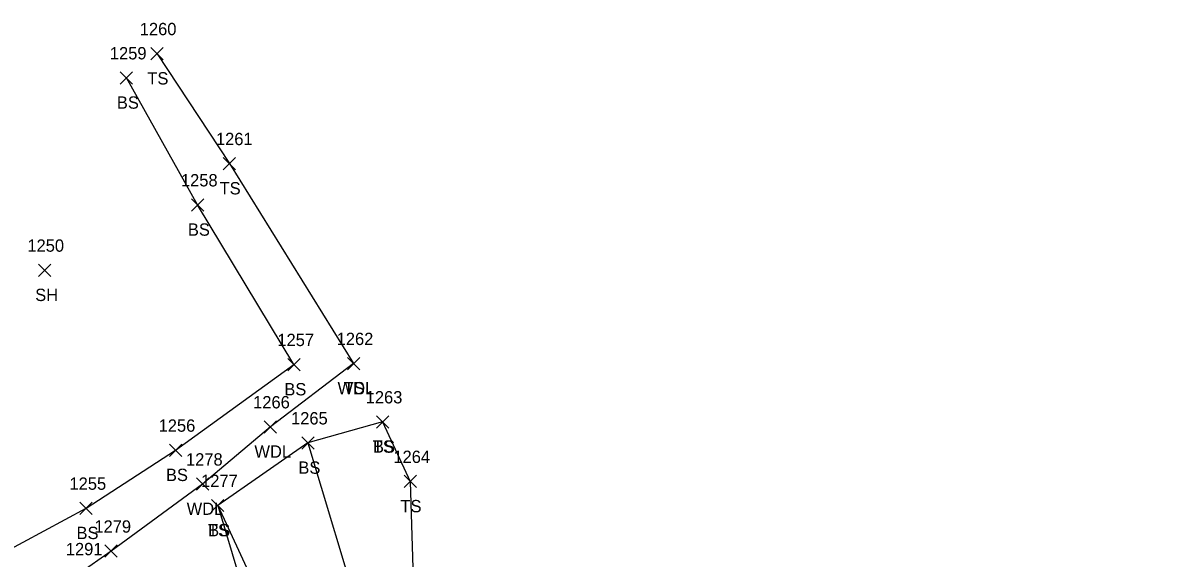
# Model space of a CAD drawing. Extents: x 1505656 to 1508446, y 700805 to 703031.
# Drawn here: x 1506221.6 to 1506405.5, y 702417.6 to 702504.5 of the extents above; entities that cross this region are included whole.
import ezdxf

# ---------------------------------------------------------------- set-up
doc = ezdxf.new("R2010")
doc.units = 0
for name, color, linetype in [('L_A', 7, 'Continuous'), ('L_I', 7, 'Continuous'), ('L_TIC', 7, 'Continuous'), ('LAWA', 7, 'Continuous'), ('LELB', 7, 'Continuous')]:
    doc.layers.add(name, color=color, linetype=linetype)

msp = doc.modelspace()

# ---------------------------------------------------------------- linework, layer by layer
at = {"layer": 'L_TIC'}
for points in [[(1506242.38, 702498.45), (1506244.38, 702500.45)], [(1506244.38, 702498.45), (1506242.38, 702500.45)], [(1506237.41, 702494.52), (1506239.41, 702496.52)], [(1506239.41, 702494.52), (1506237.41, 702496.52)], [(1506254.1, 702480.61), (1506256.1, 702482.61)], [(1506256.1, 702480.61), (1506254.1, 702482.61)], [(1506248.93, 702473.91), (1506250.93, 702475.91)], [(1506250.93, 702473.91), (1506248.93, 702475.91)], [(1506224.11, 702463.31), (1506226.11, 702465.31)], [(1506226.11, 702463.31), (1506224.11, 702465.31)], [(1506264.57, 702448), (1506266.57, 702450)], [(1506266.57, 702448), (1506264.57, 702450)], [(1506274.24, 702448.17), (1506276.24, 702450.17)], [(1506276.24, 702448.17), (1506274.24, 702450.17)], [(1506274.24, 702448.17), (1506276.24, 702450.17)], [(1506276.24, 702448.17), (1506274.24, 702450.17)], [(1506278.95, 702438.7), (1506280.95, 702440.7)], [(1506280.95, 702438.7), (1506278.95, 702440.7)], [(1506278.95, 702438.7), (1506280.95, 702440.7)], [(1506280.95, 702438.7), (1506278.95, 702440.7)], [(1506260.75, 702437.89), (1506262.75, 702439.89)], [(1506262.75, 702437.89), (1506260.75, 702439.89)], [(1506266.84, 702435.28), (1506268.84, 702437.28)], [(1506268.84, 702435.28), (1506266.84, 702437.28)], [(1506266.84, 702435.28), (1506268.84, 702437.28)], [(1506268.84, 702435.28), (1506266.84, 702437.28)], [(1506245.37, 702434.1), (1506247.37, 702436.1)], [(1506247.37, 702434.1), (1506245.37, 702436.1)], [(1506249.75, 702428.61), (1506251.75, 702430.61)], [(1506251.75, 702428.61), (1506249.75, 702430.61)], [(1506283.44, 702429.03), (1506285.44, 702431.03)], [(1506285.44, 702429.03), (1506283.44, 702431.03)], [(1506230.86, 702424.68), (1506232.86, 702426.68)], [(1506232.86, 702424.68), (1506230.86, 702426.68)], [(1506252.21, 702425.13), (1506254.21, 702427.13)], [(1506254.21, 702425.13), (1506252.21, 702427.13)], [(1506252.21, 702425.13), (1506254.21, 702427.13)], [(1506254.21, 702425.13), (1506252.21, 702427.13)], [(1506234.9, 702417.72), (1506236.9, 702419.72)], [(1506236.9, 702417.72), (1506234.9, 702419.72)]]:
    msp.add_lwpolyline(points, dxfattribs=at)
at = {"layer": 'LAWA'}
msp.add_lwpolyline([(1506275.24, 702449.17), (1506261.75, 702438.89), (1506250.75, 702429.61), (1506235.9, 702418.72), (1506230.7, 702415.06), (1506212.16, 702405.1), (1506208.12, 702393.47), (1506218.42, 702374.74), (1506247.87, 702338.8), (1506266.24, 702310.55), (1506278.03, 702304.31), (1506298.88, 702279.97), (1506302.6, 702266.31), (1506313.38, 702252.19), (1506318.56, 702232.87), (1506330.23, 702213.69), (1506343.85, 702212.06)], dxfattribs=at)
at = {"layer": 'LELB'}
for points in [[(1506243.38, 702499.45), (1506255.1, 702481.61), (1506275.24, 702449.17)], [(1506214.77, 702416.52), (1506231.86, 702425.68), (1506246.37, 702435.1), (1506265.57, 702449), (1506249.93, 702474.91), (1506238.41, 702495.52)], [(1506279.95, 702439.7), (1506267.84, 702436.28), (1506253.21, 702426.13), (1506264.28, 702402.29), (1506251.57, 702402.37), (1506255.75, 702388.87), (1506251.31, 702384.2), (1506237.54, 702397.93), (1506236.65, 702398.94), (1506230.36, 702406.23), (1506222.93, 702395.29)], [(1506279.95, 702439.7), (1506284.44, 702430.03), (1506285.02, 702410.74), (1506298.06, 702388.06), (1506299.08, 702386.26), (1506311.3, 702366.5), (1506322.79, 702353.27), (1506338.1, 702332.04), (1506351.08, 702310.42), (1506360.84, 702301.33), (1506364.51, 702285.15), (1506386.04, 702285.24), (1506401, 702288.71), (1506405.46, 702278.13)], [(1506267.84, 702436.28), (1506276.64, 702406.98), (1506291.98, 702385.58), (1506306.89, 702360.34), (1506312.14, 702350.35)], [(1506253.21, 702426.13), (1506258.94, 702406.92), (1506246.14, 702404.88), (1506251.32, 702391.32), (1506249.5, 702390.01), (1506239.73, 702401.28), (1506230.7, 702415.06)]]:
    msp.add_lwpolyline(points, dxfattribs=at)

# ---------------------------------------------------------------- texts
at = {"layer": 'L_A'}
for s, p in [('TS', (1506241.79, 702494.45)), ('BS', (1506236.85, 702490.52)), ('TS', (1506253.51, 702476.61)), ('BS', (1506248.37, 702469.91)), ('SH', (1506223.6, 702459.31)), ('BS', (1506264.01, 702444)), ('WDL', (1506272.65, 702444.17)), ('TS', (1506273.65, 702444.17)), ('TS', (1506278.36, 702434.7)), ('BS', (1506278.39, 702434.7)), ('WDL', (1506259.16, 702433.89)), ('BS', (1506266.29, 702431.28)), ('BS', (1506266.29, 702431.28)), ('BS', (1506244.81, 702430.1)), ('WDL', (1506248.17, 702424.61)), ('TS', (1506282.85, 702425.03)), ('BS', (1506230.3, 702420.68)), ('TS', (1506251.62, 702421.13)), ('BS', (1506251.65, 702421.13))]:
    msp.add_text(s, height=2, dxfattribs=at).set_placement(p)
at = {"layer": 'L_I'}
for s, p in [('1260', (1506240.56, 702502.45)), ('1259', (1506235.71, 702498.52)), ('1261', (1506252.92, 702484.61)), ('1258', (1506247.24, 702477.91)), ('1250', (1506222.33, 702467.31)), ('1257', (1506262.88, 702452)), ('1262', (1506272.5, 702452.17)), ('1262', (1506272.5, 702452.17)), ('1266', (1506258.95, 702441.89)), ('1263', (1506277.21, 702442.7)), ('1263', (1506277.21, 702442.7)), ('1265', (1506265.1, 702439.28)), ('1265', (1506265.1, 702439.28)), ('1256', (1506243.62, 702438.1)), ('1264', (1506281.7, 702433.03)), ('1278', (1506248.06, 702432.61)), ('1277', (1506250.51, 702429.13)), ('1277', (1506250.51, 702429.13)), ('1255', (1506229.16, 702428.68)), ('1279', (1506233.2, 702421.72)), ('1291', (1506228.57, 702418.06)), ('1291', (1506228.57, 702418.06))]:
    msp.add_text(s, height=2, dxfattribs=at).set_placement(p)

doc.saveas('drawing.dxf')
